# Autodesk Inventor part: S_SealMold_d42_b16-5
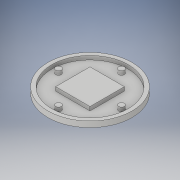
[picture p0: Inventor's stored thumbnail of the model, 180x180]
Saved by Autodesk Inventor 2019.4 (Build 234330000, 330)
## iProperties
Created: 2020-06
Part Number: S_SealMold_d42_b16-5
Material: Generisch
Document SubType Name: Modeling
Designer: Ihrrik
Density: 1 g/cm^3
Appearance: Vorgabe
Author: Ihrrik
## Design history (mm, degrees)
sketch "Skizze2"
  geometry: C1 r 22 at (0, 0); 1 further point
  constraints: 1 centre point, 1 coincident
  dimensions: "d0" = 44 diameter of C1
extrude "Extrusion1" new body sketch "Skizze2" distance "d1" = 3; taper "d2" = 0 deg
sketch "Skizze3"
  geometry: L1 (-9, -9)-(9, -9); L2 (9, -9)-(9, 9); L3 (9, 9)-(-9, 9); L4 (-9, 9)-(-9, -9); L5 (0, 30.8)-(0, -30.8) reference; L6 (-30.8, 0)-(30.8, 0) reference; C1 r 1.5 at (-16.5, 0); C2 r 1.5 at (0, -16.5); C3 r 1.5 at (0, 16.5); C4 r 1.5 at (16.5, 0); C5 r 20 at (0, 0); 1 further point
  constraints: 8 end point, 5 centre point, 4 point on line, 3 equal radius, 2 parallel, 2 perpendicular, 1 coincident, 1 horizontal, 2 other
  dimensions: "d3" = 40 diameter of C5; "d4" = 18 distance between parallel lines of L3 L1; "d5" = 16.5 distance from line of L5 C1.centre; "d6" = 3 diameter of C1; "d7" = 16.5 distance of point (0, 0) C3.centre (= d5); "d8" = 16.5 distance of point (0, 0) C4.centre (= d5); "d9" = 16.5 distance from line of L6 C2.centre (= d5)
extrude "Extrusion2" cut sketch "Skizze3" distance "d10" = 2; taper "d11" = 0 deg
node "Volumenkörper1"
